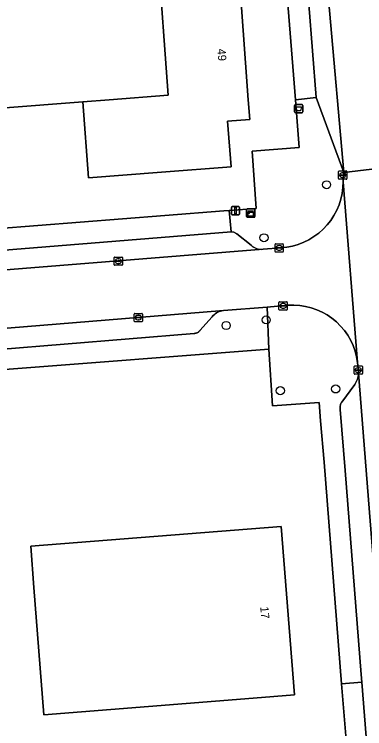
# Model space of a CAD drawing. Extents: x 157793 to 159380, y 380877 to 382313.
# Drawn here: x 158102.5 to 158144.9, y 381174 to 381260.3 of the extents above; entities that cross this region are included whole.
import ezdxf

# ---------------------------------------------------------------- set-up
doc = ezdxf.new("R2010")
doc.units = 0
for name, color, linetype in [('IMGEO_Afvalbak', 7, 'Continuous'), ('IMGEO_Boom', 7, 'Continuous'), ('IMGEO_Erf', 7, 'Continuous'), ('IMGEO_Kast', 7, 'Continuous'), ('IMGEO_Kolk', 7, 'Continuous'), ('IMGEO_Lichtmast', 7, 'Continuous'), ('IMGEO_OVBaan_gesloten', 7, 'Continuous'), ('IMGEO_Pand', 7, 'Continuous'), ('IMGEO_Pand_nummerreeks', 7, 'Continuous'), ('IMGEO_Parkeervlak_open', 7, 'Continuous'), ('IMGEO_Rijbaan_lokaal_gesloten', 7, 'Continuous'), ('IMGEO_Voetpad_open', 7, 'Continuous')]:
    doc.layers.add(name, color=color, linetype=linetype)

msp = doc.modelspace()

# ---------------------------------------------------------------- linework, layer by layer
at = {"layer": 'IMGEO_Afvalbak'}
for p, q in [((158136.4, 381248.528), (158136.4, 381249.328)), ((158136.4, 381249.328), (158136.4, 381248.528)), ((158136.5, 381249.428), (158137.29, 381249.428)), ((158137.29, 381249.428), (158136.5, 381249.428)), ((158137.39, 381249.328), (158137.39, 381248.528)), ((158137.39, 381248.528), (158137.39, 381249.328)), ((158137.29, 381248.428), (158136.5, 381248.428)), ((158136.5, 381248.428), (158137.29, 381248.428))]:
    msp.add_line(p, q, dxfattribs=at)
msp.add_lwpolyline([(158136.543, 381249.142), (158137.247, 381249.142), (158137.098, 381248.672), (158136.692, 381248.672), (158136.543, 381249.142)], dxfattribs=at)
for centre, start, end in [((158136.5, 381249.328), 90, 180), ((158136.5, 381249.328), 90, 180), ((158137.29, 381249.328), 0, 90), ((158137.29, 381249.328), 360, 90), ((158136.5, 381248.528), 180, 270), ((158136.5, 381248.528), 180, 270), ((158137.29, 381248.528), 270, 0), ((158137.29, 381248.528), 270, 0)]:
    msp.add_arc(centre, 0.1, start, end, dxfattribs=at)
at = {"layer": 'IMGEO_Boom'}
for centre in [(158140.263, 381239.735), (158132.69, 381233.328), (158132.959, 381223.392), (158128.119, 381222.722), (158134.666, 381214.837), (158141.36, 381215.05)]:
    msp.add_circle(centre, 0.489, dxfattribs=at)
at = {"layer": 'IMGEO_Erf'}
for points in [[(158117.931, 381295.704), (158119.036, 381280.745), (158118.876, 381280.733), (158119.84, 381267.681), (158129.392, 381268.386), (158129.694, 381264.293), (158128.73, 381264.222), (158128.832, 381262.833), (158129.832, 381262.907), (158130.795, 381250), (158130.974, 381247.604), (158128.29, 381247.398), (158128.714, 381241.897), (158120.298, 381241.248), (158111.474, 381240.568), (158110.766, 381249.754), (158090.893, 381248.222), (158090.756, 381250), (158087.398, 381293.448)], [(158106.078, 381175.673), (158104.865, 381191.045), (158104.472, 381196.029), (158134.762, 381198.418), (158136.368, 381178.062), (158131.384, 381177.669)]]:
    msp.add_lwpolyline(points, close=True, dxfattribs=at)
for points in [[(157997.859, 381279.57), (158000, 381252.62), (158013.029, 381253.565), (158013.303, 381250), (158014.495, 381234.507), (158014.577, 381234.444), (158031.565, 381235.712), (158032.105, 381228.956), (158032.381, 381228.979), (158037.807, 381229.413), (158044.705, 381229.949), (158092.128, 381233.777), (158100.182, 381234.397), (158120.703, 381236.005), (158127.831, 381236.564), (158128.465, 381236.609), (158131.749, 381236.844), (158131.257, 381243.784), (158136.941, 381244.249), (158136.484, 381250), (158135.122, 381267.156)], [(158147.913, 381107.409), (158147.053, 381118.043), (158146.695, 381122.56), (158144.586, 381149.315), (158143.395, 381163.444), (158142.048, 381179.413), (158139.953, 381206.198), (158139.541, 381211.176), (158139.385, 381213.413), (158133.712, 381213.005), (158133.295, 381219.868), (158100.813, 381217.341), (158099.611, 381217.247), (158052.783, 381213.5)]]:
    msp.add_lwpolyline(points, dxfattribs=at)
at = {"layer": 'IMGEO_Kast'}
for p, q in [((158130.592, 381235.878), (158130.592, 381236.719)), ((158130.592, 381236.719), (158130.592, 381235.878)), ((158130.667, 381236.803), (158131.508, 381236.803)), ((158131.508, 381236.803), (158130.667, 381236.803)), ((158131.592, 381236.728), (158131.592, 381235.887)), ((158131.592, 381235.887), (158131.592, 381236.728)), ((158131.517, 381235.803), (158130.676, 381235.803)), ((158130.676, 381235.803), (158131.517, 381235.803))]:
    msp.add_line(p, q, dxfattribs=at)
for points in [[(158130.787, 381236.593), (158131.387, 381236.593), (158131.387, 381236.508), (158130.787, 381236.508), (158130.787, 381236.593)], [(158130.787, 381236.418), (158131.387, 381236.418), (158131.387, 381235.929), (158130.787, 381235.929), (158130.787, 381236.418)]]:
    msp.add_lwpolyline(points, dxfattribs=at)
msp.add_circle((158130.871, 381236.267), 0.0377, dxfattribs=at)
for centre, start, end in [((158130.67, 381236.725), 92.4484, 184.28452), ((158130.67, 381236.725), 92.4484, 184.28452), ((158131.514, 381236.725), 2.4484, 94.28452), ((158131.514, 381236.725), 2.4484, 94.28452), ((158130.67, 381235.881), 182.4484, 274.28452), ((158130.67, 381235.881), 182.4484, 274.28452), ((158131.514, 381235.881), 272.4484, 4.28452), ((158131.514, 381235.881), 272.4484, 4.28452)]:
    msp.add_arc(centre, 0.0779, start, end, dxfattribs=at)
at = {"layer": 'IMGEO_Kolk'}
for p, q in [((158141.719, 381240.472), (158141.719, 381241.324)), ((158141.794, 381241.398), (158142.646, 381241.398)), ((158142.207, 381241.178), (158142.232, 381241.178)), ((158142.72, 381241.324), (158142.72, 381240.472)), ((158142.646, 381240.398), (158141.794, 381240.398)), ((158141.978, 381240.892), (158141.978, 381240.904)), ((158142.416, 381240.855), (158142.018, 381240.855)), ((158142.021, 381240.941), (158142.419, 381240.941)), ((158142.23, 381240.618), (158142.205, 381240.618)), ((158142.462, 381240.904), (158142.462, 381240.892)), ((158134.027, 381231.669), (158134.027, 381232.521)), ((158134.102, 381232.595), (158134.954, 381232.595)), ((158134.515, 381232.375), (158134.54, 381232.375)), ((158135.028, 381232.521), (158135.028, 381231.669)), ((158134.954, 381231.595), (158134.102, 381231.595)), ((158134.286, 381232.089), (158134.286, 381232.101)), ((158134.724, 381232.052), (158134.326, 381232.052)), ((158134.329, 381232.138), (158134.727, 381232.138)), ((158134.538, 381231.815), (158134.513, 381231.815)), ((158134.77, 381232.101), (158134.77, 381232.089)), ((158114.57, 381230.068), (158114.57, 381230.92)), ((158114.645, 381230.994), (158115.497, 381230.994)), ((158115.058, 381230.774), (158115.083, 381230.774)), ((158115.571, 381230.92), (158115.571, 381230.068)), ((158115.497, 381229.994), (158114.645, 381229.994)), ((158114.829, 381230.488), (158114.829, 381230.5)), ((158115.267, 381230.451), (158114.869, 381230.451)), ((158114.872, 381230.537), (158115.27, 381230.537)), ((158115.081, 381230.214), (158115.056, 381230.214)), ((158115.313, 381230.5), (158115.313, 381230.488)), ((158134.506, 381224.664), (158134.506, 381225.516)), ((158134.581, 381225.59), (158135.433, 381225.59)), ((158135.507, 381225.516), (158135.507, 381224.664)), ((158134.765, 381225.084), (158134.765, 381225.096)), ((158135.203, 381225.047), (158134.805, 381225.047)), ((158134.808, 381225.133), (158135.206, 381225.133)), ((158135.017, 381224.81), (158134.992, 381224.81)), ((158134.994, 381225.37), (158135.019, 381225.37)), ((158135.249, 381225.096), (158135.249, 381225.084)), ((158116.991, 381223.249), (158116.991, 381224.101)), ((158117.066, 381224.175), (158117.918, 381224.175)), ((158117.479, 381223.955), (158117.504, 381223.955)), ((158117.992, 381224.101), (158117.992, 381223.249)), ((158135.433, 381224.59), (158134.581, 381224.59)), ((158117.918, 381223.175), (158117.066, 381223.175)), ((158117.25, 381223.669), (158117.25, 381223.681)), ((158117.688, 381223.632), (158117.29, 381223.632)), ((158117.293, 381223.718), (158117.691, 381223.718)), ((158117.502, 381223.395), (158117.477, 381223.395)), ((158117.734, 381223.681), (158117.734, 381223.669)), ((158143.598, 381216.901), (158143.598, 381217.753)), ((158143.673, 381217.827), (158144.525, 381217.827)), ((158144.599, 381217.753), (158144.599, 381216.901)), ((158144.525, 381216.827), (158143.673, 381216.827)), ((158143.857, 381217.321), (158143.857, 381217.333)), ((158144.295, 381217.284), (158143.897, 381217.284)), ((158143.9, 381217.37), (158144.298, 381217.37)), ((158144.109, 381217.047), (158144.084, 381217.047)), ((158144.086, 381217.607), (158144.111, 381217.607)), ((158144.341, 381217.333), (158144.341, 381217.321))]:
    msp.add_line(p, q, dxfattribs=at)
for points in [[(158141.719, 381240.472), (158141.719, 381241.324)], [(158141.794, 381241.398), (158142.646, 381241.398)], [(158142.72, 381241.324), (158142.72, 381240.472)], [(158142.646, 381240.398), (158141.794, 381240.398)], [(158134.027, 381231.669), (158134.027, 381232.521)], [(158134.102, 381232.595), (158134.954, 381232.595)], [(158135.028, 381232.521), (158135.028, 381231.669)], [(158134.954, 381231.595), (158134.102, 381231.595)], [(158114.57, 381230.068), (158114.57, 381230.92)], [(158114.645, 381230.994), (158115.497, 381230.994)], [(158115.571, 381230.92), (158115.571, 381230.068)], [(158115.497, 381229.994), (158114.645, 381229.994)], [(158134.506, 381224.664), (158134.506, 381225.516)], [(158134.581, 381225.59), (158135.433, 381225.59)], [(158135.507, 381225.516), (158135.507, 381224.664)], [(158116.991, 381223.249), (158116.991, 381224.101)], [(158117.066, 381224.175), (158117.918, 381224.175)], [(158117.992, 381224.101), (158117.992, 381223.249)], [(158135.433, 381224.59), (158134.581, 381224.59)], [(158117.918, 381223.175), (158117.066, 381223.175)], [(158143.598, 381216.901), (158143.598, 381217.753)], [(158143.673, 381217.827), (158144.525, 381217.827)], [(158144.599, 381217.753), (158144.599, 381216.901)], [(158144.525, 381216.827), (158143.673, 381216.827)]]:
    msp.add_lwpolyline(points, dxfattribs=at)
for centre, radius, start, end in [((158141.796, 381241.322), 0.0765, 91.55205, 178.44795), ((158141.796, 381241.322), 0.0765, 91.55205, 178.44795), ((158142.644, 381241.322), 0.0765, 1.55205, 88.44795), ((158142.644, 381241.322), 0.0765, 1.55205, 88.44795), ((158141.796, 381240.474), 0.0765, 181.55205, 268.44795), ((158141.796, 381240.474), 0.0765, 181.55205, 268.44795), ((158142.018, 381240.901), 0.0403, 85.87752, 175.75265), ((158142.015, 381240.891), 0.0366, 178.93798, 274.71019), ((158142.419, 381240.898), 0.043, 264.86636, 352.45326), ((158142.423, 381240.903), 0.0386, 1.73085, 96.63898), ((158142.644, 381240.474), 0.0765, 271.55205, 358.44795), ((158142.644, 381240.474), 0.0765, 271.55205, 358.44795), ((158134.104, 381232.519), 0.0765, 91.55205, 178.44795), ((158134.104, 381232.519), 0.0765, 91.55205, 178.44795), ((158134.952, 381232.519), 0.0765, 1.55205, 88.44795), ((158134.952, 381232.519), 0.0765, 1.55205, 88.44795), ((158134.104, 381231.671), 0.0765, 181.55205, 268.44795), ((158134.104, 381231.671), 0.0765, 181.55205, 268.44795), ((158134.326, 381232.098), 0.0403, 85.87752, 175.75265), ((158134.323, 381232.088), 0.0366, 178.93798, 274.71019), ((158134.727, 381232.095), 0.043, 264.86636, 352.45326), ((158134.731, 381232.1), 0.0386, 1.73085, 96.63898), ((158134.952, 381231.671), 0.0765, 271.55205, 358.44795), ((158134.952, 381231.671), 0.0765, 271.55205, 358.44795), ((158114.647, 381230.918), 0.0765, 91.55205, 178.44795), ((158114.647, 381230.918), 0.0765, 91.55205, 178.44795), ((158115.495, 381230.918), 0.0765, 1.55205, 88.44795), ((158115.495, 381230.918), 0.0765, 1.55205, 88.44795), ((158114.647, 381230.07), 0.0765, 181.55205, 268.44795), ((158114.647, 381230.07), 0.0765, 181.55205, 268.44795), ((158114.869, 381230.497), 0.0403, 85.87752, 175.75265), ((158114.866, 381230.487), 0.0366, 178.93798, 274.71019), ((158115.27, 381230.494), 0.043, 264.86636, 352.45326), ((158115.274, 381230.499), 0.0386, 1.73085, 96.63898), ((158115.495, 381230.07), 0.0765, 271.55205, 358.44795), ((158115.495, 381230.07), 0.0765, 271.55205, 358.44795), ((158134.583, 381225.514), 0.0765, 91.55205, 178.44795), ((158134.583, 381225.514), 0.0765, 91.55205, 178.44795), ((158135.431, 381225.514), 0.0765, 1.55205, 88.44795), ((158135.431, 381225.514), 0.0765, 1.55205, 88.44795), ((158134.583, 381224.666), 0.0765, 181.55205, 268.44795), ((158134.583, 381224.666), 0.0765, 181.55205, 268.44795), ((158134.805, 381225.093), 0.0403, 85.87752, 175.75265), ((158134.802, 381225.083), 0.0366, 178.93798, 274.71019), ((158135.206, 381225.09), 0.043, 264.86636, 352.45326), ((158135.21, 381225.095), 0.0386, 1.73085, 96.63898), ((158135.431, 381224.666), 0.0765, 271.55205, 358.44795), ((158135.431, 381224.666), 0.0765, 271.55205, 358.44795), ((158117.068, 381224.099), 0.0765, 91.55205, 178.44795), ((158117.068, 381224.099), 0.0765, 91.55205, 178.44795), ((158117.916, 381224.099), 0.0765, 1.55205, 88.44795), ((158117.916, 381224.099), 0.0765, 1.55205, 88.44795), ((158117.068, 381223.251), 0.0765, 181.55205, 268.44795), ((158117.068, 381223.251), 0.0765, 181.55205, 268.44795), ((158117.29, 381223.678), 0.0403, 85.87752, 175.75265), ((158117.287, 381223.668), 0.0366, 178.93798, 274.71019), ((158117.691, 381223.675), 0.043, 264.86636, 352.45326), ((158117.695, 381223.68), 0.0386, 1.73085, 96.63898), ((158117.916, 381223.251), 0.0765, 271.55205, 358.44795), ((158117.916, 381223.251), 0.0765, 271.55205, 358.44795), ((158143.675, 381217.751), 0.0765, 91.55205, 178.44795), ((158143.675, 381217.751), 0.0765, 91.55205, 178.44795), ((158144.523, 381217.751), 0.0765, 1.55205, 88.44795), ((158144.523, 381217.751), 0.0765, 1.55205, 88.44795), ((158143.675, 381216.903), 0.0765, 181.55205, 268.44795), ((158143.675, 381216.903), 0.0765, 181.55205, 268.44795), ((158143.897, 381217.33), 0.0403, 85.87752, 175.75265), ((158143.894, 381217.32), 0.0366, 178.93798, 274.71019), ((158144.298, 381217.327), 0.043, 264.86636, 352.45326), ((158144.302, 381217.332), 0.0386, 1.73085, 96.63898), ((158144.523, 381216.903), 0.0765, 271.55205, 358.44795), ((158144.523, 381216.903), 0.0765, 271.55205, 358.44795)]:
    msp.add_arc(centre, radius, start, end, dxfattribs=at)
for centre, major_axis, ratio, start_param, end_param in [((158142.206, 381240.898), (-0.387, 0.002), 0.722429, 4.712389, 7.853982), ((158142.231, 381240.898), (-0.39, 0.002), 0.717154, 1.570796, 4.712389), ((158134.514, 381232.095), (-0.387, 0.002), 0.722429, 4.712389, 7.853982), ((158134.539, 381232.095), (-0.39, 0.002), 0.717154, 1.570796, 4.712389), ((158115.057, 381230.494), (-0.387, 0.002), 0.722429, 4.712389, 7.853982), ((158115.082, 381230.494), (-0.39, 0.002), 0.717154, 1.570796, 4.712389), ((158134.993, 381225.09), (-0.387, 0.002), 0.722429, 4.712389, 7.853982), ((158135.018, 381225.09), (-0.39, 0.002), 0.717154, 1.570796, 4.712389), ((158117.478, 381223.675), (-0.387, 0.002), 0.722429, 4.712389, 7.853982), ((158117.503, 381223.675), (-0.39, 0.002), 0.717154, 1.570796, 4.712389), ((158144.085, 381217.327), (-0.387, 0.002), 0.722429, 4.712389, 7.853982), ((158144.11, 381217.327), (-0.39, 0.002), 0.717154, 1.570796, 4.712389)]:
    msp.add_ellipse(centre, major_axis=major_axis, ratio=ratio, start_param=start_param, end_param=end_param, dxfattribs=at)
at = {"layer": 'IMGEO_Lichtmast'}
for p, q in [((158128.744, 381236.188), (158128.744, 381236.988)), ((158128.744, 381236.988), (158128.744, 381236.188)), ((158128.844, 381237.088), (158129.634, 381237.088)), ((158129.634, 381237.088), (158128.844, 381237.088)), ((158129.734, 381236.988), (158129.734, 381236.188)), ((158129.734, 381236.188), (158129.734, 381236.988)), ((158129.634, 381236.088), (158128.844, 381236.088)), ((158128.844, 381236.088), (158129.634, 381236.088))]:
    msp.add_line(p, q, dxfattribs=at)
msp.add_lwpolyline([(158129.164, 381236.963), (158129.314, 381236.963), (158129.314, 381236.213), (158129.164, 381236.213), (158129.164, 381236.963)], dxfattribs=at)
for centre, start, end in [((158128.844, 381236.988), 90, 180), ((158128.844, 381236.988), 90, 180), ((158129.634, 381236.988), 0, 90), ((158129.634, 381236.988), 360, 90), ((158128.844, 381236.188), 180, 270), ((158128.844, 381236.188), 180, 270), ((158129.634, 381236.188), 270, 0), ((158129.634, 381236.188), 270, 0)]:
    msp.add_arc(centre, 0.1, start, end, dxfattribs=at)
at = {"layer": 'IMGEO_OVBaan_gesloten'}
msp.add_lwpolyline([(158138.872, 381280.436), (158137.665, 381267.241), (158139.011, 381250.296), (158142.335, 381241.215)], close=True, dxfattribs=at)
at = {"layer": 'IMGEO_Pand'}
for points in [[(158110.766, 381249.754), (158113.957, 381250), (158121.105, 381250.551), (158119.84, 381267.681), (158118.876, 381280.733), (158119.036, 381280.745), (158117.931, 381295.704), (158087.398, 381293.448), (158090.756, 381250), (158090.893, 381248.222)], [(158110.766, 381249.754), (158111.474, 381240.568), (158120.298, 381241.248), (158128.714, 381241.897), (158128.29, 381247.398), (158130.974, 381247.604), (158130.795, 381250), (158129.832, 381262.907), (158128.832, 381262.833), (158128.73, 381264.222), (158129.694, 381264.293), (158129.392, 381268.386), (158119.84, 381267.681), (158121.105, 381250.551), (158113.957, 381250)], [(158104.865, 381191.045), (158106.078, 381175.673), (158131.384, 381177.669), (158136.368, 381178.062), (158134.762, 381198.418), (158104.472, 381196.029)]]:
    msp.add_lwpolyline(points, close=True, dxfattribs=at)
at = {"layer": 'IMGEO_Parkeervlak_open'}
for points in [[(158131.125, 381232.426), (158129.413, 381233.805), (158129.04, 381233.982), (158128.703, 381234.052), (158099.292, 381231.658), (158093.581, 381231.208), (158044.966, 381227.324), (158043.737, 381227.226), (158039.187, 381226.861), (158031.753, 381226.266)], [(158028.252, 381223.804), (158029.109, 381223.718), (158030.031, 381223.709), (158030.666, 381223.751), (158132.588, 381231.929)], [(158124.251, 381221.757), (158124.327, 381221.762), (158124.403, 381221.773), (158124.478, 381221.791), (158124.55, 381221.815), (158124.62, 381221.846), (158124.687, 381221.884), (158124.75, 381221.927), (158124.81, 381221.975), (158124.864, 381222.029), (158124.914, 381222.087), (158124.931, 381222.109), (158126.416, 381223.777), (158126.519, 381223.896), (158126.647, 381224.021), (158126.786, 381224.134), (158126.935, 381224.235), (158127.092, 381224.321), (158127.256, 381224.394), (158127.426, 381224.451), (158127.6, 381224.493), (158127.777, 381224.519), (158047.254, 381217.965)], [(158050.989, 381215.798), (158051.586, 381215.846), (158100.609, 381219.811), (158124.251, 381221.757)], [(158144.104, 381216.957), (158144.106, 381216.916), (158144.104, 381216.739), (158144.085, 381216.563), (158144.052, 381216.389), (158144.003, 381216.219), (158143.939, 381216.054), (158143.86, 381215.895), (158143.768, 381215.744), (158143.662, 381215.602), (158142.097, 381213.444), (158142.045, 381213.362), (158142, 381213.276), (158141.963, 381213.186), (158141.934, 381213.093), (158141.914, 381212.998), (158141.902, 381212.902), (158141.899, 381212.804), (158141.905, 381212.705), (158141.92, 381212.567), (158142.51, 381205.179), (158144.457, 381180.531), (158144.53, 381179.608), (158146.968, 381148.6)], [(158152.577, 381109.874), (158144.104, 381216.957)]]:
    msp.add_lwpolyline(points, dxfattribs=at)
msp.add_arc((158132.439, 381233.893), 1.97, 228.14839, 274.32503, dxfattribs=at)
at = {"layer": 'IMGEO_Rijbaan_lokaal_gesloten'}
for points in [[(158138.872, 381280.436), (158142.335, 381241.215), (158149.14, 381242.015), (158148.922, 381244.787), (158148.512, 381250), (158148.273, 381253.043), (158148.225, 381253.262), (158146.678, 381273.28)], [(158047.254, 381217.965), (158127.777, 381224.519), (158133.058, 381224.955), (158135.584, 381225.164), (158135.609, 381225.166), (158136.315, 381225.184), (158137.021, 381225.14), (158137.719, 381225.032), (158138.405, 381224.863), (158139.073, 381224.633), (158139.718, 381224.344), (158140.335, 381223.999), (158140.918, 381223.6), (158141.463, 381223.151), (158141.966, 381222.654), (158142.423, 381222.115), (158142.829, 381221.537), (158143.183, 381220.925), (158143.48, 381220.284), (158143.719, 381219.619), (158143.897, 381218.935), (158144.014, 381218.239), (158142.257, 381240.094), (158142.228, 381239.384), (158142.136, 381238.679), (158141.982, 381237.986), (158141.766, 381237.309), (158141.491, 381236.654), (158141.158, 381236.026), (158140.77, 381235.43), (158140.331, 381234.872), (158139.844, 381234.355), (158139.312, 381233.883), (158138.741, 381233.461), (158138.134, 381233.091), (158137.496, 381232.778), (158136.833, 381232.522), (158136.15, 381232.327), (158135.452, 381232.194), (158134.745, 381232.123), (158132.588, 381231.929), (158030.666, 381223.751)]]:
    msp.add_lwpolyline(points, dxfattribs=at)
msp.add_lwpolyline([(158150.099, 381229.806), (158149.14, 381242.015), (158142.335, 381241.215), (158142.257, 381240.094), (158144.014, 381218.239), (158144.068, 381217.534), (158144.104, 381216.957), (158152.577, 381109.874), (158152.586, 381109.766), (158154.041, 381092.18), (158154.127, 381091.136), (158154.165, 381090.674), (158154.179, 381090.5), (158156.578, 381060.941), (158164.18, 381061.511), (158163.518, 381070.346), (158163.463, 381070.73), (158160.906, 381093.85), (158160.761, 381094.91), (158160.265, 381101.527)], close=True, dxfattribs=at)
at = {"layer": 'IMGEO_Voetpad_open'}
for points in [[(158137.665, 381267.241), (158135.122, 381267.156), (158136.484, 381250), (158139.011, 381250.296)], [(158099.292, 381231.658), (158128.703, 381234.052), (158128.465, 381236.609), (158127.831, 381236.564), (158120.703, 381236.005), (158100.182, 381234.397), (158092.128, 381233.777), (158044.705, 381229.949), (158044.966, 381227.324), (158093.581, 381231.208)], [(158143.719, 381219.619), (158143.48, 381220.284), (158143.183, 381220.925), (158142.829, 381221.537), (158142.423, 381222.115), (158141.966, 381222.654), (158141.463, 381223.151), (158140.918, 381223.6), (158140.335, 381223.999), (158139.718, 381224.344), (158139.073, 381224.633), (158138.405, 381224.863), (158137.719, 381225.032), (158137.021, 381225.14), (158136.315, 381225.184), (158135.609, 381225.166), (158135.584, 381225.164), (158133.058, 381224.955), (158133.295, 381219.868), (158133.712, 381213.005), (158139.385, 381213.413), (158139.541, 381211.176), (158139.953, 381206.198), (158142.048, 381179.413), (158144.53, 381179.608), (158144.457, 381180.531), (158142.51, 381205.179), (158141.92, 381212.567), (158141.905, 381212.705), (158141.899, 381212.804), (158141.902, 381212.902), (158141.914, 381212.998), (158141.934, 381213.093), (158141.963, 381213.186), (158142, 381213.276), (158142.045, 381213.362), (158142.097, 381213.444), (158143.662, 381215.602), (158143.768, 381215.744), (158143.86, 381215.895), (158143.939, 381216.054), (158144.003, 381216.219), (158144.052, 381216.389), (158144.085, 381216.563), (158144.104, 381216.739), (158144.106, 381216.916), (158144.104, 381216.957), (158144.068, 381217.534), (158144.014, 381218.239), (158143.897, 381218.935)]]:
    msp.add_lwpolyline(points, close=True, dxfattribs=at)
for points in [[(158142.228, 381239.384), (158142.257, 381240.094), (158142.335, 381241.215), (158139.011, 381250.296), (158136.484, 381250), (158136.941, 381244.249), (158131.257, 381243.784), (158131.749, 381236.844), (158128.465, 381236.609), (158128.703, 381234.052), (158129.04, 381233.982), (158129.413, 381233.805), (158131.125, 381232.426)], [(158132.588, 381231.929), (158134.745, 381232.123), (158135.452, 381232.194), (158136.15, 381232.327), (158136.833, 381232.522), (158137.496, 381232.778), (158138.134, 381233.091), (158138.741, 381233.461), (158139.312, 381233.883), (158139.844, 381234.355), (158140.331, 381234.872), (158140.77, 381235.43), (158141.158, 381236.026), (158141.491, 381236.654), (158141.766, 381237.309), (158141.982, 381237.986), (158142.136, 381238.679), (158142.228, 381239.384)], [(158100.813, 381217.341), (158133.295, 381219.868), (158133.058, 381224.955), (158127.777, 381224.519), (158127.6, 381224.493), (158127.426, 381224.451), (158127.256, 381224.394), (158127.092, 381224.321), (158126.935, 381224.235), (158126.786, 381224.134), (158126.647, 381224.021), (158126.519, 381223.896), (158126.416, 381223.777), (158124.931, 381222.109), (158124.914, 381222.087), (158124.864, 381222.029), (158124.81, 381221.975), (158124.75, 381221.927), (158124.687, 381221.884), (158124.62, 381221.846), (158124.55, 381221.815), (158124.478, 381221.791), (158124.403, 381221.773), (158124.327, 381221.762), (158124.251, 381221.757), (158100.609, 381219.811)], [(158146.968, 381148.6), (158144.53, 381179.608), (158142.048, 381179.413), (158143.395, 381163.444), (158144.586, 381149.315), (158146.695, 381122.56), (158147.053, 381118.043), (158147.913, 381107.409), (158149.076, 381091.874), (158154.041, 381092.18), (158152.586, 381109.766), (158152.577, 381109.874)]]:
    msp.add_lwpolyline(points, dxfattribs=at)
msp.add_arc((158132.439, 381233.893), 1.97, 228.14839, 274.32503, dxfattribs=at)

# ---------------------------------------------------------------- texts
at = {"layer": 'IMGEO_Pand_nummerreeks'}
for s, rotation, p in [('49', 274.26784, (158127.048, 381256.144)), ('17', 274.51104, (158132.237, 381188.715))]:
    msp.add_text(s, height=1, rotation=rotation, dxfattribs=at).set_placement(p)

doc.saveas('drawing.dxf')
